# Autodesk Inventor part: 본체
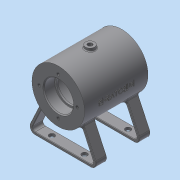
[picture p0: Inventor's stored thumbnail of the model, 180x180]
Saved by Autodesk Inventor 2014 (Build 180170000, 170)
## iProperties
Created: 2021-12
Part Number: 본체
Material: 일반
Document SubType Name: Modeling
Designer: dg
Density: 1 g/cm^3
Appearance: 기본값
Author: dg
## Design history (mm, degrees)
sketch "스케치1"
  geometry: C1 r 29 at (0, 0); 1 further point
  constraints: 1 centre point, 1 coincident
  dimensions: "d0" = 58 diameter of C1
extrude "돌출1" new body sketch "스케치1" stored distance "d1" = 70; taper "d2" = 0 deg
node "작업 평면1"
sketch "스케치2"
  geometry: L1 (-40, -55)-(40, -55); L2 (40, -55)-(22.743, -17.993); L3 (-40, -55)-(-22.743, -17.993); L4 (20.574, -20.438)-(35.291, -52); L5 (35.291, -52)-(-35.291, -52); L6 (-35.291, -52)-(-20.574, -20.438); A1 r 29 centre (0, 0) between (-22.743, -17.993) and (22.743, -17.993) reference; 2 further points
  constraints: 12 end point, 4 point on circle, 2 horizontal, 1 equal length, 1 midpoint, 1 vertical alignment
  dimensions: "d4" = 80 distance of L1.start L1.end; "d5" = 55 distance from line of point (0, 0) L1; "d6" = 65 deg angle of L1 L2; "d7" = 65 deg angle of L1 L3; "d8" = 3 distance between parallel lines of L2 L4; "d9" = 3 distance between parallel lines of L1 L5; "d11" = 65 deg angle of L6 L5
extrude "돌출2" join sketch "스케치2" distance "d12" = 12; taper "d13" = 0 deg
node "작업 평면2"
sketch "스케치3"
  geometry: L1 (-35, 29)-(-35, -29) reference; L2 (35, -29)-(35, 29) reference; L3 (-35, 0)-(35, 0); L4 (-35, 16)-(-23, 16); L5 (-23, 16)-(-23, 14); L6 (-23, 14)-(-21, 14); L7 (-21, 14)-(-21, 21); L8 (-21, 21)-(21, 21); L9 (21, 21)-(21, 14); L10 (21, 14)-(23, 14); L11 (23, 14)-(23, 16); L12 (23, 16)-(35, 16); 1 further point
  constraints: 20 end point, 4 parallel, 4 perpendicular, 2 horizontal alignment, 2 midpoint, 2 point on line, 1 collinear, 1 vertical
  dimensions: "d14" = 12 distance of L4.start L4.end; "d15" = 2 distance of L9.end L10.end; "d16" = 42 distance of L7.end L8.end; "d17" = 28 diameter of L10 L3; "d18" = 32 diameter of L12 L3; "d19" = 42 diameter of L8 L3
revolve "회전1" sketch "스케치3" stored, may be unused: angle "d20" = 90 deg
node "작업 평면3"
sketch "스케치4"
  geometry: L1 (0, 0)-(10.945, -30.07); L2 (0, 0)-(0, -44.396)
  constraints: 4 end point, 1 vertical
  dimensions: "d21" = 20 deg angle of L2 L1; "d22" = 32 distance of L1.start L1.end
node "작업 평면4"
sketch "스케치5"
  geometry: C1 r 6 at (0, 0); 1 further point
  constraints: 1 centre point, 1 coincident
  dimensions: "d23" = 12 diameter of C1
extrude "돌출3" join sketch "스케치5" distance "d24" = 10; taper "d25" = 0 deg
node "작업 평면5"
sketch "스케치6"
  geometry: C1 r 5 at (0, 0); 1 further point
  constraints: 1 centre point, 1 coincident
  dimensions: "d27" = 10 diameter of C1
extrude "돌출4" join sketch "스케치6" distance "d28" = 10; taper "d29" = 0 deg
fillet "모깎기1" dims "d30" = 6
fillet "모깎기2" dims "d31" = 3
fillet "모깎기3" dims "d32" = 0.5
fillet "모깎기4" dims "d33" = 3
sketch "스케치7"
  geometry: L1 (61.164, 0.5)-(66.664, 0.5) reference; L2 (48.582, -5.5)-(12.582, -5.5); C1 r 3 at (48.582, -5.5); C2 r 3 at (12.582, -5.5); 3 further points
  constraints: 2 centre point, 2 end point, 1 equal radius, 1 horizontal alignment, 1 midpoint, 1 parallel, 1 vertical alignment
  dimensions: "d34" = 6 distance from line of L1 L2.start; "d35" = 36 distance of L2.end L2.start; "d36" = 6 diameter of C1
extrude "돌출5" cut sketch "스케치7" distance "d37" = 10; taper "d38" = 0 deg
sketch "스케치8"
  geometry: C1 r 16 at (0, 0) reference; 1 further point
  constraints: 1 vertical alignment
  dimensions: "d40" = 21 distance of C1.centre point (0, -21)
hole "구멍1" sketch "스케치8" at (0, -21) diameter "d41" = 3.242; stored, may be unused: countersink angle "d45" = 90 deg, drill point angle "d47" = 118 deg; dims "d42" = 8, "d43" = 4, "d44" = 2, "d46" = 10
sketch "스케치9"
  geometry: C1 r 5 at (0, 0) reference; 1 further point
  constraints: 1 coincident
hole "구멍2" sketch "스케치9" at (0, 0) diameter "d51" = 4.917; stored, may be unused: countersink angle "d55" = 90 deg, drill point angle "d57" = 118 deg; dims "d52" = 6, "d53" = 4, "d54" = 2, "d56" = 8
sketch "스케치10"
  geometry: C1 r 5 at (0, 0) reference; C2 r 1.5 at (0, 0)
  constraints: 1 centre point, 1 coincident
  dimensions: "d58" = 3 diameter of C2
extrude "돌출6" cut sketch "스케치10" distance "d59" = 30; taper "d60" = 0 deg
fillet "모깎기5" dims "d61" = 1
sketch "스케치11"
  geometry: C1 r 6 at (0, 0) reference; 1 further point
  constraints: 1 coincident
hole "구멍3" sketch "스케치11" at (0, 0) diameter "d62" = 4.917; stored, may be unused: countersink angle "d66" = 90 deg, drill point angle "d68" = 118 deg; dims "d63" = 32, "d64" = 4, "d65" = 2, "d67" = 8
fillet "모깎기6" dims "d69" = 3
fillet "모깎기7" dims "d70" = 0.3
chamfer "모따기1" distance "d71" = 1; stored, may be unused: second distance "d72" = 2, angle "d73" = 45 deg
chamfer "모따기2" distance "d74" = 1; stored, may be unused: second distance "d75" = 2, angle "d76" = 45 deg
node "작업 평면6"
feature "엠보싱1" dims "d0" = 58, "d80" = 0.5, "d81" = 0
node "솔리드1"
mirror "대칭1"
mirror "대칭2"
pattern_circular "원형 패턴1" dims angle "d49" = 360 deg
mirror "대칭3"
node "투영된 루프1"
sketch "스케치12"
  geometry: L1 (-35, 29)-(-35, -29) reference; L2 (-35, 29)-(35, 29) reference; 4 further points
  constraints: 2 midpoint, 1 horizontal alignment, 1 vertical alignment, 1 other
  dimensions: "d82" = 35 distance from line of L1 point (0, 0) (derived); "d83" = 29 distance from line of L2 point (0, 0) (derived)
other parameters: "d3" = -5, "d26" = 32, "d77" = 29.5
